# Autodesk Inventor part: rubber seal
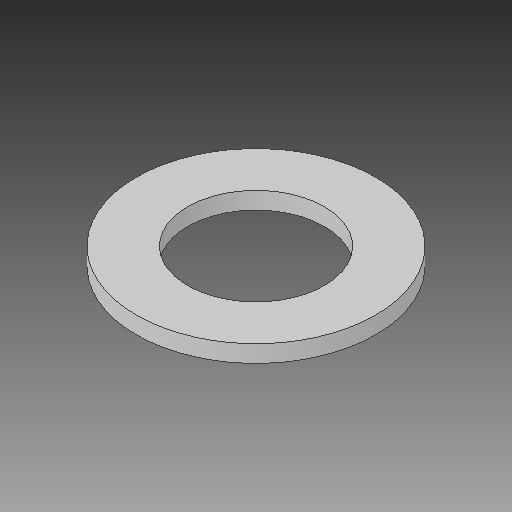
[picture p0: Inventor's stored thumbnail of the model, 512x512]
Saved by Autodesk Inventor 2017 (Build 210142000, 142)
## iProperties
Created: 2020-03
Part Number: rubber seal
Material: Generic
Document SubType Name: Modeling
Designer: user
Density: 1 g/cm^3
Appearance: Default
Mass: 0.103673 g
Surface Area: 2.7646 cm^2
Volume: 0.103673 cm^3
Author: user
Revision Number: ANY
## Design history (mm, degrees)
feature "Boss-Extrude1"
body "Solid1"
